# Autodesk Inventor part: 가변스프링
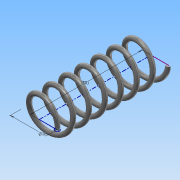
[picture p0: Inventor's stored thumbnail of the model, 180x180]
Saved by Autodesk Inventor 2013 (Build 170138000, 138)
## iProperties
Created: 2018-11
Part Number: 가변스프링
Material: 강철, 탄소
Document SubType Name: Modeling
Designer: Administrator
Density: 7.87 g/cm^3
Mass: 8.6244 g
Surface Area: 22.1693 cm^2
Volume: 1.09586 cm^3
Author: Administrator
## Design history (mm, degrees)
sketch "스케치1"
  geometry: L1 (0, 0)-(-8, 0); L2 (-8, 0)-(-8, 43.5); L3 (-8, 43.5)-(0, 43.5); C1 r 1 at (0, 0); 1 further point
  constraints: 6 end point, 1 centre point, 1 coincident, 1 horizontal, 1 parallel, 1 perpendicular, 1 vertical alignment
  dimensions: "d0" = 2 diameter of C1; "d1" = 16 diameter of point (0, 0) L2; "d2" = 43.5 distance of L1.end L2.end (derived)
feature "코일1" pitch "d3" = 10; turns "d5" = 7; dims "d4" = 43.5 (= d2), "d6" = 0, angle "d7" = 90 deg, angle "d8" = 90 deg, "d9" = 0, "d10" = 0
sketch "스케치2"
  geometry: C1 r 22.186 at (0, 0); 1 further point
  constraints: 1 centre point, 1 coincident
extrude "돌출1" cut sketch "스케치2" distance "d11" = 10; taper "d12" = 0 deg
node "작업 평면1"
sketch "스케치3"
  geometry: C1 r 24.048 at (-8, 0); 1 further point
  constraints: 1 centre point, 1 coincident
extrude "돌출2" cut sketch "스케치3" distance "d13" = 10; taper "d14" = 0 deg
node "솔리드1"
